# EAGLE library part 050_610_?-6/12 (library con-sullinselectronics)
.050 DIP EDGE CARD CONNECTOR .050 [1.27mm] CONTACT CENTERS .610" INSULATEOR HEIGHT Source: .050 DIP EDGE CARD.pdf
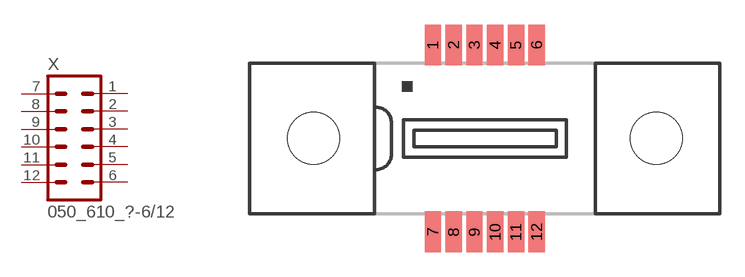
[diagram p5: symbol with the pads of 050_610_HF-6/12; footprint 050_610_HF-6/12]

Designator prefix X

## 050_610_HF-6/12 (OC_FARNELL: unknown; OC_NEWARK: unknown)  [050_610_HF-6/12]
1  1  pas
2  2  pas
3  3  pas
4  4  pas
5  5  pas
6  6  pas
7  7  pas
8  8  pas
9  9  pas
10  10  pas
11  11  pas
12  12  pas

## Footprint 050_610_HF-6/12 (pad centres in mm)
.050 DIP EDGE CARD CONNECTOR SURFACE MOUNT .050 [1.27mm] CONTACT CENTERS .610" INSULATEOR HEIGHT Source: .050 DIP EDGE CARD.pdf
smd 1 x 2.5: 1 -3.175,5.715; 2 -1.905,5.715; 3 -0.635,5.715; 4 0.635,5.715; 5 1.905,5.715; 6 3.175,5.715; 7 -3.175,-5.715; 8 -1.905,-5.715; 9 -0.635,-5.715; 10 0.635,-5.715; 11 1.905,-5.715; 12 3.175,-5.715
hole 3.18 at -10.49,0
hole 3.18 at 10.49,0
